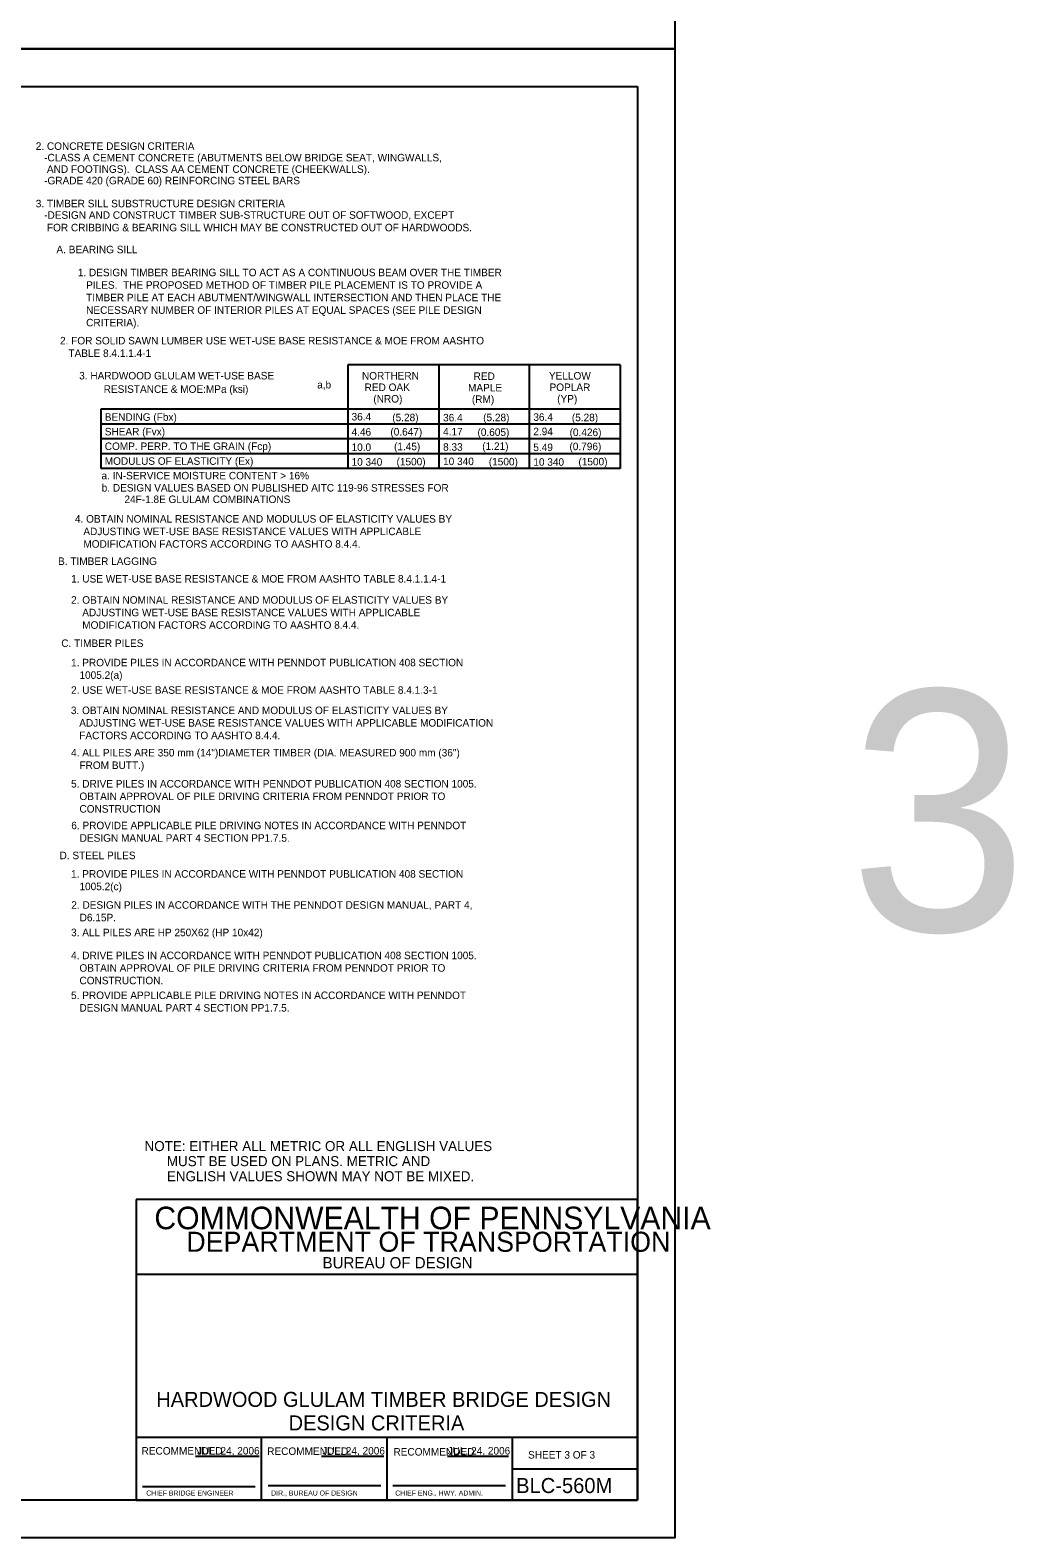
# Model space of a CAD drawing. Extents: x 637594 to 640253, y 297247 to 298527.
# Drawn here: x 639860 to 640253, y 297247 to 297849 of the extents above; entities that cross this region are included whole.
import ezdxf

# ---------------------------------------------------------------- set-up
doc = ezdxf.new("R2010")
doc.units = 0
for name, color, linetype in [('2', 7, 'Continuous'), ('3', 7, 'Continuous'), ('4', 7, 'Continuous'), ('53', 7, 'Continuous'), ('PLT-BNDY', 7, 'Continuous')]:
    doc.layers.add(name, color=color, linetype=linetype)

msp = doc.modelspace()

# ---------------------------------------------------------------- linework, layer by layer
at = {"layer": '2'}
for p, q in [((639316.46, 297826.46), (640102.46, 297826.46)), ((640102.46, 297826.46), (640102.46, 297262.46)), ((639986.95, 297715.45), (639986.95, 297674.06)), ((640095.54, 297715.45), (639986.95, 297715.45)), ((640023.26, 297715.45), (640023.26, 297674.06)), ((640059.33, 297715.45), (640059.33, 297674.06)), ((640095.54, 297715.45), (640095.54, 297674.06)), ((640095.54, 297697.71), (639888.34, 297697.71)), ((639888.34, 297697.71), (639888.34, 297674.06)), ((640095.54, 297691.8), (639888.34, 297691.8)), ((640095.54, 297685.89), (639888.34, 297685.89)), ((640095.54, 297679.97), (639888.34, 297679.97)), ((640095.54, 297674.06), (639888.34, 297674.06)), ((640102.46, 297382.46), (639902.46, 297382.46)), ((639902.46, 297382.46), (639902.46, 297262.46)), ((640102.46, 297262.46), (640102.46, 297382.46)), ((640102.46, 297352.46), (639902.46, 297352.46)), ((640102.46, 297287.46), (639902.46, 297287.46)), ((639952.46, 297262.46), (639952.46, 297287.46)), ((640002.46, 297287.46), (640002.46, 297262.46)), ((640052.46, 297287.46), (640052.46, 297262.46)), ((639926.11, 297280.03), (639951.49, 297280.03)), ((639976.38, 297280.03), (640001.27, 297280.03)), ((640026.65, 297280.03), (640051.06, 297280.03)), ((640052.46, 297274.96), (640102.46, 297274.96)), ((639904.96, 297267.96), (639949.96, 297267.96)), ((639955.08, 297268.33), (640000.08, 297268.33)), ((640004.83, 297268.33), (640049.83, 297268.33)), ((640102.46, 297262.46), (639316.46, 297262.46)), ((639902.46, 297262.46), (640102.46, 297262.46))]:
    msp.add_line(p, q, dxfattribs=at)
at = {"layer": 'PLT-BNDY'}
for points in [[(639276.46, 298435.46), (640117.46, 298435.46), (640117.46, 297841.46), (639276.46, 297841.46)], [(639276.46, 297841.46), (640117.46, 297841.46), (640117.46, 297247.46), (639276.46, 297247.46)]]:
    msp.add_lwpolyline(points, close=True, dxfattribs=at)

# ---------------------------------------------------------------- texts
at = {"layer": '2'}
for s, height, p in [('3. HARDWOOD GLULAM WET-USE BASE', 3.0001, (639879.72, 297709.61)), ('NORTHERN', 3, (639992.54, 297709.58)), ('YELLOW', 3, (640067.16, 297709.58)), ('RESISTANCE & MOE:MPa (ksi)', 3.0001, (639889.5, 297704.26)), ('a,b', 3, (639974.68, 297706.01)), ('RED OAK', 3, (639993.61, 297704.99)), ('MAPLE', 3, (640034.87, 297704.82)), ('RED', 3, (640037.11, 297709.41)), ('POPLAR', 3, (640067.4, 297704.99)), ('(NRO)', 3, (639997.1, 297700.39)), ('(RM)', 3, (640036.42, 297700.22)), ('(YP)', 3, (640070.45, 297700.39)), ('BENDING (Fbx)', 3.0001, (639889.92, 297693.1)), ('36.4', 3, (639988.4, 297693.24)), ('(5.28)', 3, (640004.65, 297692.94)), ('36.4', 3, (640024.92, 297692.86)), ('(5.28)', 3, (640040.91, 297692.94)), ('36.4', 3, (640060.93, 297693.09)), ('(5.28)', 3, (640076.3, 297692.94)), ('SHEAR (Fvx)', 3.0001, (639889.92, 297687.28)), ('4.46', 3, (639988.4, 297687.15)), ('(0.647)', 3, (640003.89, 297687.22)), ('4.17', 3, (640024.92, 297687.26)), ('(0.605)', 3, (640038.65, 297687.07)), ('2.94', 3, (640060.93, 297687.36)), ('(0.426)', 3, (640075.41, 297687.03)), ('COMP. PERP. TO THE GRAIN (Fcp)', 3.0001, (639889.92, 297681.46)), ('10.0', 3, (639988.4, 297681.06)), ('(1.45)', 3, (640005.35, 297681.37)), ('8.33', 3, (640024.92, 297681.16)), ('(1.21)', 3, (640040.55, 297681.48)), ('5.49', 3, (640060.93, 297681.02)), ('(0.796)', 3, (640075.35, 297681.38)), ('MODULUS OF ELASTICITY (Ex)', 3.0001, (639889.92, 297675.55)), ('10 340', 3, (639988.4, 297675.21)), ('(1500)', 3, (640006.35, 297675.32)), ('10 340', 3, (640024.92, 297675.43)), ('(1500)', 3, (640043.17, 297675.32)), ('10 340', 3, (640060.93, 297675.17)), ('(1500)', 3, (640078.93, 297675.32)), ('a. IN-SERVICE MOISTURE CONTENT > 16%', 3.0001, (639888.62, 297669.73)), ('b. DESIGN VALUES BASED ON PUBLISHED AITC 119-96 STRESSES FOR', 3.0001, (639888.69, 297664.88)), ('24F-1.8E GLULAM COMBINATIONS', 3.0001, (639897.77, 297660.29)), ('COMMONWEALTH OF PENNSYLVANIA', 9, (639909.71, 297370.58)), ('DEPARTMENT OF TRANSPORTATION', 8.0002, (639922.46, 297361.58)), ('BUREAU OF DESIGN', 4.5, (639976.83, 297354.96)), ('HARDWOOD GLULAM TIMBER BRIDGE DESIGN', 5.9716, (639910.48, 297299.71)), ('DESIGN CRITERIA', 5.9716, (639963.29, 297290.32)), ('RECOMMENDED', 3, (639904.61, 297280.66)), ('JUL. 24, 2006', 3, (639926.74, 297280.69)), ('RECOMMENDED', 3, (639954.74, 297280.53)), ('JUL. 24, 2006', 3, (639976.74, 297280.69)), ('RECOMMENDED', 3, (640005.11, 297280.28)), ('JUL. 24, 2006', 3, (640026.74, 297280.69)), ('SHEET 3 OF 3', 3, (640058.83, 297279.08)), ('BLC-560M', 6, (640054.08, 297265.33)), ('CHIEF BRIDGE ENGINEER', 2.0002, (639906.46, 297264.33)), ('DIR., BUREAU OF DESIGN', 2.0002, (639956.33, 297264.33)), ('CHIEF ENG., HWY. ADMIN.', 2.0002, (640005.83, 297264.33))]:
    msp.add_text(s, height=height, dxfattribs=at).set_placement(p)
at = {"layer": '3'}
for s, p in [('NOTE: EITHER ALL METRIC OR ALL ENGLISH VALUES', (639905.78, 297401.75)), ('      MUST BE USED ON PLANS. METRIC AND', (639905.78, 297395.74)), ('      ENGLISH VALUES SHOWN MAY NOT BE MIXED.', (639905.78, 297389.73))]:
    msp.add_text(s, height=4.0058, dxfattribs=at).set_placement(p)
at = {"layer": '4'}
msp.add_text('3', height=96, dxfattribs=at).set_placement((640186.92, 297489.61))
at = {"layer": '53'}
for s, p in [('2. CONCRETE DESIGN CRITERIA', (639862.39, 297801.2)), ('   -CLASS A CEMENT CONCRETE (ABUTMENTS BELOW BRIDGE SEAT, WINGWALLS, ', (639862.39, 297796.61)), ('    AND FOOTINGS).  CLASS AA CEMENT CONCRETE (CHEEKWALLS).', (639862.39, 297792.03)), ('   -GRADE 420 (GRADE 60) REINFORCING STEEL BARS', (639862.39, 297787.45)), ('3. TIMBER SILL SUBSTRUCTURE DESIGN CRITERIA', (639862.39, 297778.28)), ('   -DESIGN AND CONSTRUCT TIMBER SUB-STRUCTURE OUT OF SOFTWOOD, EXCEPT', (639862.39, 297773.7)), ('    FOR CRIBBING & BEARING SILL WHICH MAY BE CONSTRUCTED OUT OF HARDWOODS. ', (639862.39, 297768.7)), ('A. BEARING SILL', (639870.64, 297759.94)), ('1. DESIGN TIMBER BEARING SILL TO ACT AS A CONTINUOUS BEAM OVER THE TIMBER', (639879.15, 297750.78)), ('   PILES.  THE PROPOSED METHOD OF TIMBER PILE PLACEMENT IS TO PROVIDE A', (639879.15, 297745.78)), ('   TIMBER PILE AT EACH ABUTMENT/WINGWALL INTERSECTION AND THEN PLACE THE', (639879.15, 297740.78)), ('   NECESSARY NUMBER OF INTERIOR PILES AT EQUAL SPACES (SEE PILE DESIGN', (639879.15, 297735.78)), ('   CRITERIA). ', (639879.15, 297730.78)), ('    2. FOR SOLID SAWN LUMBER USE WET-USE BASE RESISTANCE & MOE FROM AASHTO', (639867.61, 297723.58)), ('       TABLE 8.4.1.1.4-1 ', (639867.61, 297718.58)), (' 4. OBTAIN NOMINAL RESISTANCE AND MODULUS OF ELASTICITY VALUES BY', (639876.92, 297652.48)), ('    ADJUSTING WET-USE BASE RESISTANCE VALUES WITH APPLICABLE', (639876.92, 297647.48)), ('    MODIFICATION FACTORS ACCORDING TO AASHTO 8.4.4.', (639876.92, 297642.48)), ('B. TIMBER LAGGING', (639871.29, 297635.59)), ('  1. USE WET-USE BASE RESISTANCE & MOE FROM AASHTO TABLE 8.4.1.1.4-1', (639874.28, 297628.58)), ('  2. OBTAIN NOMINAL RESISTANCE AND MODULUS OF ELASTICITY VALUES BY', (639874.25, 297620.13)), ('      ADJUSTING WET-USE BASE RESISTANCE VALUES WITH APPLICABLE', (639874.25, 297615.13)), ('      MODIFICATION FACTORS ACCORDING TO AASHTO 8.4.4.', (639874.25, 297610.13)), ('C. TIMBER PILES', (639872.58, 297602.87)), ('  1. PROVIDE PILES IN ACCORDANCE WITH PENNDOT PUBLICATION 408 SECTION', (639874.25, 297595.15)), ('     1005.2(a)', (639874.25, 297590.15)), ('  2. USE WET-USE BASE RESISTANCE & MOE FROM AASHTO TABLE 8.4.1.3-1', (639874.25, 297584.18)), ('  3. OBTAIN NOMINAL RESISTANCE AND MODULUS OF ELASTICITY VALUES BY', (639874.17, 297576.09)), ('     ADJUSTING WET-USE BASE RESISTANCE VALUES WITH APPLICABLE MODIFICATION', (639874.17, 297571.09)), ('     FACTORS ACCORDING TO AASHTO 8.4.4.', (639874.17, 297566.09)), ('  4. ALL PILES ARE 350 mm (14")DIAMETER TIMBER (DIA. MEASURED 900 mm (36")', (639874.25, 297559.2)), ('     FROM BUTT.)', (639874.25, 297554.2)), ('  5. DRIVE PILES IN ACCORDANCE WITH PENNDOT PUBLICATION 408 SECTION 1005.', (639874.25, 297546.8)), ('     OBTAIN APPROVAL OF PILE DRIVING CRITERIA FROM PENNDOT PRIOR TO', (639874.25, 297541.8)), ('     CONSTRUCTION', (639874.25, 297536.79)), ('  6. PROVIDE APPLICABLE PILE DRIVING NOTES IN ACCORDANCE WITH PENNDOT', (639874.34, 297530.17)), ('     DESIGN MANUAL PART 4 SECTION PP1.7.5.', (639874.34, 297525.17)), ('D. STEEL PILES', (639871.89, 297518.21)), ('  1. PROVIDE PILES IN ACCORDANCE WITH PENNDOT PUBLICATION 408 SECTION', (639874.25, 297510.84)), ('     1005.2(c)', (639874.25, 297505.84)), ('  2. DESIGN PILES IN ACCORDANCE WITH THE PENNDOT DESIGN MANUAL, PART 4,', (639874.34, 297498.44)), ('     D6.15P.', (639874.34, 297493.44)), ('  3. ALL PILES ARE HP 250X62 (HP 10x42)', (639874.25, 297487.48)), ('  4. DRIVE PILES IN ACCORDANCE WITH PENNDOT PUBLICATION 408 SECTION 1005.', (639874.25, 297478.31)), ('     OBTAIN APPROVAL OF PILE DRIVING CRITERIA FROM PENNDOT PRIOR TO', (639874.25, 297473.31)), ('     CONSTRUCTION.', (639874.25, 297468.31)), ('  5. PROVIDE APPLICABLE PILE DRIVING NOTES IN ACCORDANCE WITH PENNDOT', (639874.25, 297462.4)), ('     DESIGN MANUAL PART 4 SECTION PP1.7.5.', (639874.25, 297457.4))]:
    msp.add_text(s, height=3.0001, dxfattribs=at).set_placement(p)

doc.saveas('drawing.dxf')
